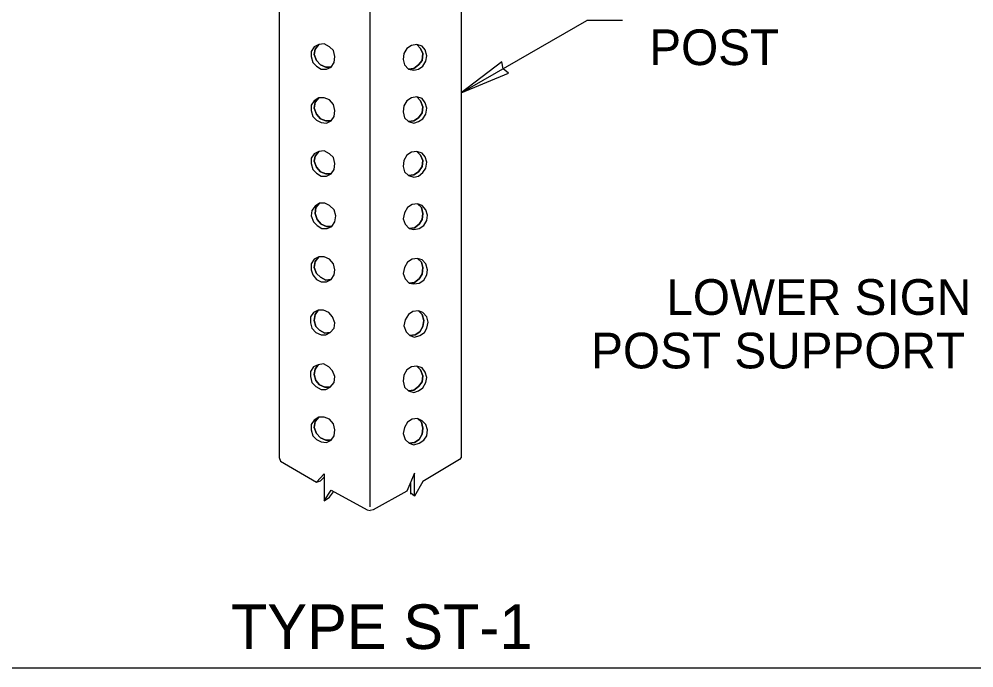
# Model space of a CAD drawing. Extents: x 99862 to 103680, y 99470 to 102076.
# Drawn here: x 100290 to 100717.9, y 99999.5 to 100290.3 of the extents above; entities that cross this region are included whole.
import ezdxf

# ---------------------------------------------------------------- set-up
doc = ezdxf.new("R2010")
doc.units = 0
for name, color, linetype in [('Level 1', 7, 'Continuous'), ('Level 15', 7, 'Continuous'), ('Level 2', 7, 'Continuous'), ('Level 20', 7, 'Continuous')]:
    doc.layers.add(name, color=color, linetype=linetype)

msp = doc.modelspace()

# ---------------------------------------------------------------- linework, layer by layer
at = {"layer": 'Level 1'}
msp.add_lwpolyline([(99862, 99999.5), (103151, 99999.5), (103151, 102075.5), (99862, 102075.5)], close=True, dxfattribs=at)
at = {"layer": 'Level 15'}
for p in [(100488.14, 100257.23), (100560.43, 100289.73)]:
    msp.add_line(p, (100544.43, 100289.73), dxfattribs=at)
msp.add_lwpolyline([(100488.14, 100257.23), (100509.4, 100266.06), (100506.99, 100268.12), (100506.42, 100271.23)], close=True, dxfattribs=at)
at = {"layer": 'Level 2'}
for p, q in [((100406.49, 100420.53), (100406.49, 100093.86)), ((100488.14, 100420.6), (100488.14, 100093.86)), ((100447.31, 100071.74), (100447.31, 100397.53)), ((100424.33, 100278.9), (100422.27, 100277.89)), ((100424.33, 100278.9), (100422.61, 100276.89)), ((100422.61, 100276.89), (100424.33, 100278.9)), ((100426.73, 100279.23), (100424.33, 100278.9)), ((100429.13, 100277.89), (100426.73, 100279.23)), ((100468.24, 100278.9), (100465.84, 100278.56)), ((100469.95, 100277.22), (100468.24, 100278.9)), ((100470.64, 100278.23), (100468.24, 100278.9)), ((100468.24, 100278.9), (100469.95, 100277.22)), ((100422.27, 100277.89), (100420.9, 100275.88)), ((100420.9, 100275.88), (100420.9, 100273.53)), ((100422.61, 100276.89), (100422.27, 100274.54)), ((100422.27, 100274.54), (100422.61, 100276.89)), ((100422.27, 100274.54), (100423.3, 100271.86)), ((100423.3, 100271.86), (100422.27, 100274.54)), ((100430.85, 100276.22), (100429.13, 100277.89)), ((100431.53, 100273.53), (100430.85, 100276.22)), ((100462.41, 100274.87), (100462.06, 100272.19)), ((100463.78, 100277.22), (100462.41, 100274.87)), ((100465.84, 100278.56), (100463.78, 100277.22)), ((100470.98, 100274.87), (100469.95, 100277.22)), ((100469.95, 100277.22), (100470.98, 100274.87)), ((100472.01, 100276.55), (100470.64, 100278.23)), ((100470.64, 100271.86), (100470.98, 100274.87)), ((100470.98, 100274.87), (100470.64, 100271.86)), ((100472.7, 100273.87), (100472.01, 100276.55)), ((100420.9, 100273.53), (100421.58, 100270.85)), ((100421.58, 100270.85), (100423.3, 100269.18)), ((100423.3, 100271.86), (100425.01, 100269.85)), ((100425.01, 100269.85), (100423.3, 100271.86)), ((100429.82, 100268.84), (100431.19, 100270.85)), ((100431.19, 100270.85), (100431.53, 100273.53)), ((100462.06, 100272.19), (100462.75, 100269.85)), ((100468.93, 100269.85), (100470.64, 100271.86)), ((100470.64, 100271.86), (100468.93, 100269.85)), ((100470.98, 100269.18), (100472.36, 100271.52)), ((100472.36, 100271.52), (100472.7, 100273.87)), ((100423.3, 100269.18), (100425.36, 100267.84)), ((100425.01, 100269.85), (100427.42, 100268.84)), ((100427.42, 100268.84), (100425.01, 100269.85)), ((100425.36, 100267.84), (100427.76, 100267.84)), ((100427.42, 100268.84), (100429.82, 100268.84)), ((100429.82, 100268.84), (100427.42, 100268.84)), ((100427.76, 100267.84), (100429.82, 100268.84)), ((100462.75, 100269.85), (100464.47, 100267.84)), ((100464.47, 100267.84), (100466.87, 100268.17)), ((100466.87, 100268.17), (100464.47, 100267.84)), ((100464.47, 100267.84), (100466.87, 100267.5)), ((100466.87, 100268.17), (100468.93, 100269.85)), ((100468.93, 100269.85), (100466.87, 100268.17)), ((100466.87, 100267.5), (100468.93, 100267.84)), ((100468.93, 100267.84), (100470.98, 100269.18)), ((100422.27, 100253.76), (100420.9, 100251.75)), ((100424.33, 100255.1), (100422.27, 100253.76)), ((100422.61, 100253.09), (100422.27, 100250.4)), ((100422.27, 100250.4), (100422.61, 100253.09)), ((100424.33, 100255.1), (100422.61, 100253.09)), ((100422.61, 100253.09), (100424.33, 100255.1)), ((100426.73, 100255.1), (100424.33, 100255.1)), ((100429.13, 100254.09), (100426.73, 100255.1)), ((100430.85, 100252.08), (100429.13, 100254.09)), ((100463.78, 100253.76), (100462.41, 100251.41)), ((100465.84, 100255.1), (100463.78, 100253.76)), ((100468.24, 100255.43), (100465.84, 100255.1)), ((100469.95, 100253.76), (100468.24, 100255.43)), ((100470.64, 100254.76), (100468.24, 100255.43)), ((100468.24, 100255.43), (100469.95, 100253.76)), ((100470.98, 100251.07), (100469.95, 100253.76)), ((100469.95, 100253.76), (100470.98, 100251.07)), ((100472.01, 100252.75), (100470.64, 100254.76)), ((100420.9, 100251.75), (100420.9, 100249.4)), ((100420.9, 100249.4), (100421.58, 100246.72)), ((100422.27, 100250.4), (100423.3, 100247.72)), ((100423.3, 100247.72), (100422.27, 100250.4)), ((100431.53, 100249.4), (100430.85, 100252.08)), ((100431.19, 100246.72), (100431.53, 100249.4)), ((100462.41, 100251.41), (100462.06, 100248.73)), ((100462.06, 100248.73), (100462.75, 100246.05)), ((100470.64, 100248.39), (100470.98, 100251.07)), ((100470.98, 100251.07), (100470.64, 100248.39)), ((100472.7, 100250.4), (100472.01, 100252.75)), ((100472.36, 100247.72), (100472.7, 100250.4)), ((100421.58, 100246.72), (100423.3, 100245.04)), ((100423.3, 100247.72), (100425.01, 100245.71)), ((100425.01, 100245.71), (100423.3, 100247.72)), ((100423.3, 100245.04), (100425.36, 100244.04)), ((100425.01, 100245.71), (100427.42, 100244.71)), ((100427.42, 100244.71), (100425.01, 100245.71)), ((100427.42, 100244.71), (100429.82, 100244.71)), ((100429.82, 100244.71), (100427.42, 100244.71)), ((100427.76, 100243.7), (100429.82, 100244.71)), ((100429.82, 100244.71), (100431.19, 100246.72)), ((100462.75, 100246.05), (100464.47, 100244.37)), ((100464.47, 100244.37), (100466.87, 100244.71)), ((100466.87, 100244.71), (100464.47, 100244.37)), ((100466.87, 100244.71), (100468.93, 100246.05)), ((100468.93, 100246.05), (100466.87, 100244.71)), ((100468.93, 100246.05), (100470.64, 100248.39)), ((100470.64, 100248.39), (100468.93, 100246.05)), ((100468.93, 100244.37), (100470.98, 100245.71)), ((100470.98, 100245.71), (100472.36, 100247.72)), ((100425.36, 100244.04), (100427.76, 100243.7)), ((100464.47, 100244.37), (100466.87, 100243.7)), ((100466.87, 100243.7), (100468.93, 100244.37)), ((100422.27, 100229.96), (100420.9, 100227.94)), ((100420.9, 100227.94), (100420.9, 100225.6)), ((100424.33, 100230.96), (100422.27, 100229.96)), ((100422.61, 100228.95), (100422.27, 100226.6)), ((100422.27, 100226.6), (100422.61, 100228.95)), ((100424.33, 100230.96), (100422.61, 100228.95)), ((100422.61, 100228.95), (100424.33, 100230.96)), ((100426.73, 100231.3), (100424.33, 100230.96)), ((100429.13, 100229.96), (100426.73, 100231.3)), ((100430.85, 100228.28), (100429.13, 100229.96)), ((100431.53, 100225.6), (100430.85, 100228.28)), ((100463.78, 100229.29), (100462.41, 100226.94)), ((100465.84, 100230.63), (100463.78, 100229.29)), ((100468.24, 100230.96), (100465.84, 100230.63)), ((100469.95, 100229.29), (100468.24, 100230.96)), ((100470.64, 100230.29), (100468.24, 100230.96)), ((100468.24, 100230.96), (100469.95, 100229.29)), ((100470.98, 100226.94), (100469.95, 100229.29)), ((100469.95, 100229.29), (100470.98, 100226.94)), ((100472.01, 100228.62), (100470.64, 100230.29)), ((100472.7, 100226.27), (100472.01, 100228.62)), ((100420.9, 100225.6), (100421.58, 100222.92)), ((100422.27, 100226.6), (100423.3, 100223.92)), ((100423.3, 100223.92), (100422.27, 100226.6)), ((100423.3, 100223.92), (100425.01, 100221.91)), ((100425.01, 100221.91), (100423.3, 100223.92)), ((100431.19, 100222.92), (100431.53, 100225.6)), ((100462.41, 100226.94), (100462.06, 100224.26)), ((100462.06, 100224.26), (100462.75, 100221.91)), ((100468.93, 100221.91), (100470.64, 100224.26)), ((100470.64, 100224.26), (100468.93, 100221.91)), ((100470.64, 100224.26), (100470.98, 100226.94)), ((100470.98, 100226.94), (100470.64, 100224.26)), ((100470.98, 100221.58), (100472.36, 100223.59)), ((100472.36, 100223.59), (100472.7, 100226.27)), ((100421.58, 100222.92), (100423.3, 100221.24)), ((100423.3, 100221.24), (100425.36, 100219.9)), ((100425.01, 100221.91), (100427.42, 100220.91)), ((100427.42, 100220.91), (100425.01, 100221.91)), ((100425.36, 100219.9), (100427.76, 100219.9)), ((100427.42, 100220.91), (100429.82, 100220.91)), ((100429.82, 100220.91), (100427.42, 100220.91)), ((100427.76, 100219.9), (100429.82, 100220.91)), ((100429.82, 100220.91), (100431.19, 100222.92)), ((100462.75, 100221.91), (100464.47, 100220.24)), ((100464.47, 100220.24), (100466.87, 100220.57)), ((100466.87, 100220.57), (100464.47, 100220.24)), ((100464.47, 100220.24), (100466.87, 100219.56)), ((100466.87, 100220.57), (100468.93, 100221.91)), ((100468.93, 100221.91), (100466.87, 100220.57)), ((100466.87, 100219.56), (100468.93, 100219.9)), ((100468.93, 100219.9), (100470.98, 100221.58)), ((100422.61, 100206.49), (100421.24, 100204.48)), ((100424.67, 100207.83), (100422.61, 100206.49)), ((100424.67, 100207.83), (100422.96, 100205.82)), ((100422.96, 100205.82), (100424.67, 100207.83)), ((100427.07, 100207.83), (100424.67, 100207.83)), ((100429.13, 100206.83), (100427.07, 100207.83)), ((100431.19, 100204.82), (100429.13, 100206.83)), ((100466.18, 100207.16), (100464.12, 100205.82)), ((100468.58, 100207.5), (100466.18, 100207.16)), ((100470.3, 100205.82), (100468.58, 100207.5)), ((100470.64, 100206.83), (100468.58, 100207.5)), ((100468.58, 100207.5), (100470.3, 100205.82)), ((100472.36, 100204.82), (100470.64, 100206.83)), ((100421.24, 100204.48), (100420.9, 100202.13)), ((100420.9, 100202.13), (100421.93, 100199.45)), ((100422.96, 100205.82), (100422.61, 100203.14)), ((100422.61, 100203.14), (100422.96, 100205.82)), ((100422.61, 100203.14), (100423.64, 100200.46)), ((100423.64, 100200.46), (100422.61, 100203.14)), ((100431.88, 100202.13), (100431.19, 100204.82)), ((100431.53, 100199.45), (100431.88, 100202.13)), ((100462.75, 100203.47), (100462.06, 100200.79)), ((100464.12, 100205.82), (100462.75, 100203.47)), ((100470.98, 100203.14), (100470.3, 100205.82)), ((100470.3, 100205.82), (100470.98, 100203.14)), ((100470.64, 100200.46), (100470.98, 100203.14)), ((100470.98, 100203.14), (100470.64, 100200.46)), ((100473.04, 100202.47), (100472.36, 100204.82)), ((100472.7, 100200.12), (100473.04, 100202.47)), ((100421.93, 100199.45), (100423.64, 100197.78)), ((100423.64, 100200.46), (100425.36, 100198.45)), ((100425.36, 100198.45), (100423.64, 100200.46)), ((100423.64, 100197.78), (100425.7, 100196.43)), ((100425.36, 100198.45), (100427.76, 100197.44)), ((100427.76, 100197.44), (100425.36, 100198.45)), ((100427.76, 100197.44), (100430.16, 100197.44)), ((100430.16, 100197.44), (100427.76, 100197.44)), ((100428.1, 100196.43), (100430.16, 100197.44)), ((100430.16, 100197.44), (100431.53, 100199.45)), ((100462.06, 100200.79), (100463.09, 100198.45)), ((100463.09, 100198.45), (100464.81, 100196.43)), ((100467.21, 100196.77), (100469.27, 100198.45)), ((100469.27, 100198.45), (100467.21, 100196.77)), ((100469.27, 100198.45), (100470.64, 100200.46)), ((100470.64, 100200.46), (100469.27, 100198.45)), ((100469.27, 100196.43), (100471.33, 100197.78)), ((100471.33, 100197.78), (100472.7, 100200.12)), ((100425.7, 100196.43), (100428.1, 100196.43)), ((100464.81, 100196.43), (100467.21, 100196.77)), ((100467.21, 100196.77), (100464.81, 100196.43)), ((100464.81, 100196.43), (100466.87, 100196.1)), ((100466.87, 100196.1), (100469.27, 100196.43)), ((100422.27, 100182.69), (100420.9, 100180.68)), ((100420.9, 100180.68), (100420.9, 100178)), ((100424.33, 100183.7), (100422.27, 100182.69)), ((100422.61, 100181.69), (100422.27, 100179)), ((100422.27, 100179), (100422.61, 100181.69)), ((100424.33, 100183.7), (100422.61, 100181.69)), ((100422.61, 100181.69), (100424.33, 100183.7)), ((100426.73, 100183.7), (100424.33, 100183.7)), ((100429.13, 100182.69), (100426.73, 100183.7)), ((100430.85, 100180.68), (100429.13, 100182.69)), ((100431.53, 100178), (100430.85, 100180.68)), ((100464.12, 100181.35), (100462.75, 100179)), ((100466.18, 100182.69), (100464.12, 100181.35)), ((100468.58, 100183.03), (100466.18, 100182.69)), ((100470.3, 100181.35), (100468.58, 100183.03)), ((100470.64, 100182.36), (100468.58, 100183.03)), ((100468.58, 100183.03), (100470.3, 100181.35)), ((100470.98, 100179), (100470.3, 100181.35)), ((100470.3, 100181.35), (100470.98, 100179)), ((100472.36, 100180.68), (100470.64, 100182.36)), ((100473.04, 100178), (100472.36, 100180.68)), ((100420.9, 100178), (100421.58, 100175.65)), ((100422.27, 100179), (100423.3, 100176.32)), ((100423.3, 100176.32), (100422.27, 100179)), ((100423.3, 100176.32), (100425.01, 100174.65)), ((100425.01, 100174.65), (100423.3, 100176.32)), ((100431.19, 100175.65), (100431.53, 100178)), ((100462.75, 100179), (100462.06, 100176.32)), ((100462.06, 100176.32), (100463.09, 100173.98)), ((100469.27, 100173.98), (100470.64, 100175.99)), ((100470.64, 100175.99), (100469.27, 100173.98)), ((100470.64, 100175.99), (100470.98, 100179)), ((100470.98, 100179), (100470.64, 100175.99)), ((100472.7, 100175.65), (100473.04, 100178)), ((100421.58, 100175.65), (100423.3, 100173.64)), ((100423.3, 100173.64), (100425.36, 100172.63)), ((100425.01, 100174.65), (100427.42, 100173.31)), ((100427.42, 100173.31), (100425.01, 100174.65)), ((100425.36, 100172.63), (100427.76, 100172.63)), ((100427.42, 100173.31), (100429.82, 100173.64)), ((100429.82, 100173.64), (100427.42, 100173.31)), ((100427.76, 100172.63), (100429.82, 100173.64)), ((100429.82, 100173.64), (100431.19, 100175.65)), ((100463.09, 100173.98), (100464.81, 100171.96)), ((100464.81, 100171.96), (100467.21, 100172.3)), ((100467.21, 100172.3), (100464.81, 100171.96)), ((100464.81, 100171.96), (100466.87, 100171.63)), ((100466.87, 100171.63), (100469.27, 100171.96)), ((100467.21, 100172.3), (100469.27, 100173.98)), ((100469.27, 100173.98), (100467.21, 100172.3)), ((100469.27, 100171.96), (100471.33, 100173.31)), ((100471.33, 100173.31), (100472.7, 100175.65)), ((100421.93, 100158.89), (100420.56, 100156.88)), ((100423.99, 100159.9), (100421.93, 100158.89)), ((100423.99, 100159.9), (100422.61, 100157.89)), ((100422.61, 100157.89), (100423.99, 100159.9)), ((100426.39, 100159.9), (100423.99, 100159.9)), ((100428.79, 100158.89), (100426.39, 100159.9)), ((100430.5, 100156.88), (100428.79, 100158.89)), ((100466.52, 100159.23), (100464.47, 100157.89)), ((100468.93, 100159.56), (100466.52, 100159.23)), ((100470.64, 100157.89), (100468.93, 100159.56)), ((100470.98, 100158.89), (100468.93, 100159.56)), ((100468.93, 100159.56), (100470.64, 100157.89)), ((100472.7, 100156.88), (100470.98, 100158.89)), ((100420.56, 100156.88), (100420.56, 100154.2)), ((100422.61, 100157.89), (100422.27, 100155.2)), ((100422.27, 100155.2), (100422.61, 100157.89)), ((100422.27, 100155.2), (100422.96, 100152.52)), ((100422.96, 100152.52), (100422.27, 100155.2)), ((100431.53, 100154.2), (100430.5, 100156.88)), ((100463.09, 100155.54), (100462.41, 100152.86)), ((100464.47, 100157.89), (100463.09, 100155.54)), ((100471.33, 100155.2), (100470.64, 100157.89)), ((100470.64, 100157.89), (100471.33, 100155.2)), ((100470.98, 100152.52), (100471.33, 100155.2)), ((100471.33, 100155.2), (100470.98, 100152.52)), ((100473.39, 100154.53), (100472.7, 100156.88)), ((100472.7, 100151.85), (100473.39, 100154.53)), ((100420.56, 100154.2), (100421.24, 100151.85)), ((100421.24, 100151.85), (100422.96, 100149.84)), ((100422.96, 100152.52), (100424.67, 100150.85)), ((100424.67, 100150.85), (100422.96, 100152.52)), ((100424.67, 100150.85), (100427.07, 100149.5)), ((100427.07, 100149.5), (100424.67, 100150.85)), ((100429.47, 100149.84), (100431.19, 100151.85)), ((100431.19, 100151.85), (100431.53, 100154.2)), ((100462.41, 100152.86), (100463.44, 100150.18)), ((100469.61, 100150.18), (100470.98, 100152.52)), ((100470.98, 100152.52), (100469.61, 100150.18)), ((100471.67, 100149.84), (100472.7, 100151.85)), ((100422.96, 100149.84), (100425.36, 100148.83)), ((100425.36, 100148.83), (100427.42, 100148.83)), ((100427.07, 100149.5), (100429.47, 100149.84)), ((100429.47, 100149.84), (100427.07, 100149.5)), ((100427.42, 100148.83), (100429.47, 100149.84)), ((100463.44, 100150.18), (100465.15, 100148.5)), ((100465.15, 100148.5), (100467.55, 100148.83)), ((100467.55, 100148.83), (100465.15, 100148.5)), ((100465.15, 100148.5), (100467.21, 100147.83)), ((100467.21, 100147.83), (100469.61, 100148.5)), ((100467.55, 100148.83), (100469.61, 100150.18)), ((100469.61, 100150.18), (100467.55, 100148.83)), ((100469.61, 100148.5), (100471.67, 100149.84)), ((100421.93, 100134.42), (100420.56, 100132.41)), ((100423.99, 100135.43), (100421.93, 100134.42)), ((100422.61, 100133.41), (100422.27, 100131.07)), ((100422.27, 100131.07), (100422.61, 100133.41)), ((100423.99, 100135.43), (100422.61, 100133.41)), ((100422.61, 100133.41), (100423.99, 100135.43)), ((100426.39, 100135.76), (100423.99, 100135.43)), ((100428.79, 100134.42), (100426.39, 100135.76)), ((100430.5, 100132.74), (100428.79, 100134.42)), ((100465.84, 100134.42), (100463.78, 100133.08)), ((100468.24, 100134.76), (100465.84, 100134.42)), ((100469.95, 100133.08), (100468.24, 100134.76)), ((100470.64, 100134.09), (100468.24, 100134.76)), ((100468.24, 100134.76), (100469.95, 100133.08)), ((100472.01, 100132.07), (100470.64, 100134.09)), ((100420.56, 100132.41), (100420.56, 100130.06)), ((100420.56, 100130.06), (100421.24, 100127.38)), ((100422.27, 100131.07), (100422.96, 100128.39)), ((100422.96, 100128.39), (100422.27, 100131.07)), ((100431.53, 100130.06), (100430.5, 100132.74)), ((100431.19, 100127.38), (100431.53, 100130.06)), ((100462.41, 100130.73), (100462.06, 100128.05)), ((100463.78, 100133.08), (100462.41, 100130.73)), ((100470.98, 100130.4), (100469.95, 100133.08)), ((100469.95, 100133.08), (100470.98, 100130.4)), ((100470.64, 100127.72), (100470.98, 100130.4)), ((100470.98, 100130.4), (100470.64, 100127.72)), ((100472.7, 100129.73), (100472.01, 100132.07)), ((100472.36, 100127.38), (100472.7, 100129.73)), ((100421.24, 100127.38), (100422.96, 100125.7)), ((100422.96, 100128.39), (100424.67, 100126.38)), ((100424.67, 100126.38), (100422.96, 100128.39)), ((100422.96, 100125.7), (100425.36, 100124.36)), ((100424.67, 100126.38), (100427.07, 100125.37)), ((100427.07, 100125.37), (100424.67, 100126.38)), ((100427.07, 100125.37), (100429.47, 100125.37)), ((100429.47, 100125.37), (100427.07, 100125.37)), ((100427.42, 100124.36), (100429.47, 100125.37)), ((100429.47, 100125.37), (100431.19, 100127.38)), ((100462.06, 100128.05), (100462.75, 100125.37)), ((100462.75, 100125.37), (100464.47, 100123.69)), ((100466.87, 100124.03), (100468.93, 100125.7)), ((100468.93, 100125.7), (100466.87, 100124.03)), ((100468.93, 100125.7), (100470.64, 100127.72)), ((100470.64, 100127.72), (100468.93, 100125.7)), ((100468.93, 100123.69), (100470.98, 100125.03)), ((100470.98, 100125.03), (100472.36, 100127.38)), ((100425.36, 100124.36), (100427.42, 100124.36)), ((100464.47, 100123.69), (100466.87, 100124.03)), ((100466.87, 100124.03), (100464.47, 100123.69)), ((100464.47, 100123.69), (100466.87, 100123.02)), ((100466.87, 100123.02), (100468.93, 100123.69)), ((100424.33, 100111.96), (100422.27, 100110.62)), ((100424.33, 100111.96), (100422.61, 100109.95)), ((100422.61, 100109.95), (100424.33, 100111.96)), ((100426.73, 100111.96), (100424.33, 100111.96)), ((100429.13, 100110.96), (100426.73, 100111.96)), ((100422.27, 100110.62), (100420.9, 100108.61)), ((100420.9, 100108.61), (100420.9, 100106.26)), ((100422.61, 100109.95), (100422.27, 100107.27)), ((100422.27, 100107.27), (100422.61, 100109.95)), ((100430.85, 100108.94), (100429.13, 100110.96)), ((100431.53, 100106.26), (100430.85, 100108.94)), ((100464.12, 100109.61), (100462.75, 100107.27)), ((100466.18, 100110.96), (100464.12, 100109.61)), ((100468.58, 100111.29), (100466.18, 100110.96)), ((100470.3, 100109.61), (100468.58, 100111.29)), ((100470.64, 100110.28), (100468.58, 100111.29)), ((100468.58, 100111.29), (100470.3, 100109.61)), ((100470.98, 100106.93), (100470.3, 100109.61)), ((100470.3, 100109.61), (100470.98, 100106.93)), ((100472.36, 100108.61), (100470.64, 100110.28)), ((100473.04, 100106.26), (100472.36, 100108.61)), ((100420.9, 100106.26), (100421.58, 100103.58)), ((100421.58, 100103.58), (100423.3, 100101.9)), ((100422.27, 100107.27), (100423.3, 100104.59)), ((100423.3, 100104.59), (100422.27, 100107.27)), ((100423.3, 100104.59), (100425.01, 100102.57)), ((100425.01, 100102.57), (100423.3, 100104.59)), ((100429.82, 100101.57), (100431.19, 100103.58)), ((100431.19, 100103.58), (100431.53, 100106.26)), ((100462.75, 100107.27), (100462.06, 100104.59)), ((100462.06, 100104.59), (100463.09, 100101.9)), ((100469.27, 100101.9), (100470.64, 100104.25)), ((100470.64, 100104.25), (100469.27, 100101.9)), ((100470.64, 100104.25), (100470.98, 100106.93)), ((100470.98, 100106.93), (100470.64, 100104.25)), ((100471.33, 100101.57), (100472.7, 100103.58)), ((100472.7, 100103.58), (100473.04, 100106.26)), ((100423.3, 100101.9), (100425.36, 100100.9)), ((100425.01, 100102.57), (100427.42, 100101.57)), ((100427.42, 100101.57), (100425.01, 100102.57)), ((100425.36, 100100.9), (100427.76, 100100.56)), ((100427.42, 100101.57), (100429.82, 100101.57)), ((100429.82, 100101.57), (100427.42, 100101.57)), ((100427.76, 100100.56), (100429.82, 100101.57)), ((100463.09, 100101.9), (100464.81, 100100.23)), ((100464.81, 100100.23), (100467.21, 100100.56)), ((100467.21, 100100.56), (100464.81, 100100.23)), ((100464.81, 100100.23), (100466.87, 100099.56)), ((100466.87, 100099.56), (100469.27, 100100.23)), ((100467.21, 100100.56), (100469.27, 100101.9)), ((100469.27, 100101.9), (100467.21, 100100.56)), ((100469.27, 100100.23), (100471.33, 100101.57)), ((100406.49, 100093.86), (100407.18, 100092.18)), ((100407.18, 100092.18), (100423.3, 100082.8)), ((100487.45, 100092.85), (100470.98, 100083.13)), ((100488.14, 100093.86), (100487.45, 100092.85)), ((100423.3, 100082.8), (100426.73, 100086.48)), ((100426.73, 100086.48), (100426.73, 100074.42)), ((100467.21, 100086.82), (100463.78, 100078.77)), ((100467.21, 100076.43), (100467.21, 100086.82)), ((100465.5, 100077.43), (100465.5, 100082.8)), ((100470.98, 100083.13), (100467.21, 100076.43)), ((100426.73, 100074.42), (100429.82, 100079.11)), ((100429.13, 100076.09), (100430.85, 100078.44)), ((100429.82, 100079.11), (100445.94, 100070.39)), ((100463.78, 100078.77), (100448.69, 100070.39)), ((100467.21, 100076.43), (100465.5, 100077.77)), ((100426.73, 100074.42), (100429.13, 100076.09)), ((100445.94, 100070.39), (100447.31, 100070.06)), ((100448.69, 100070.39), (100447.31, 100070.06))]:
    msp.add_line(p, q, dxfattribs=at)
msp.add_lwpolyline([(100423.3, 100082.8), (100425.11, 100083.3), (100426.73, 100085.06)], dxfattribs=at)

# ---------------------------------------------------------------- texts
at = {"layer": 'Level 20'}
msp.add_text('POST', height=16, rotation=360, dxfattribs=at).set_placement((100572.43, 100269.73))
for s, height, p in [('LOWER SIGN', 16, (100580.07, 100157.76)), ('POST SUPPORT', 16, (100546.36, 100133.76)), ('TYPE ST-1', 20, (100384.88, 100007.98))]:
    msp.add_text(s, height=height, dxfattribs=at).set_placement(p)

doc.saveas('drawing.dxf')
